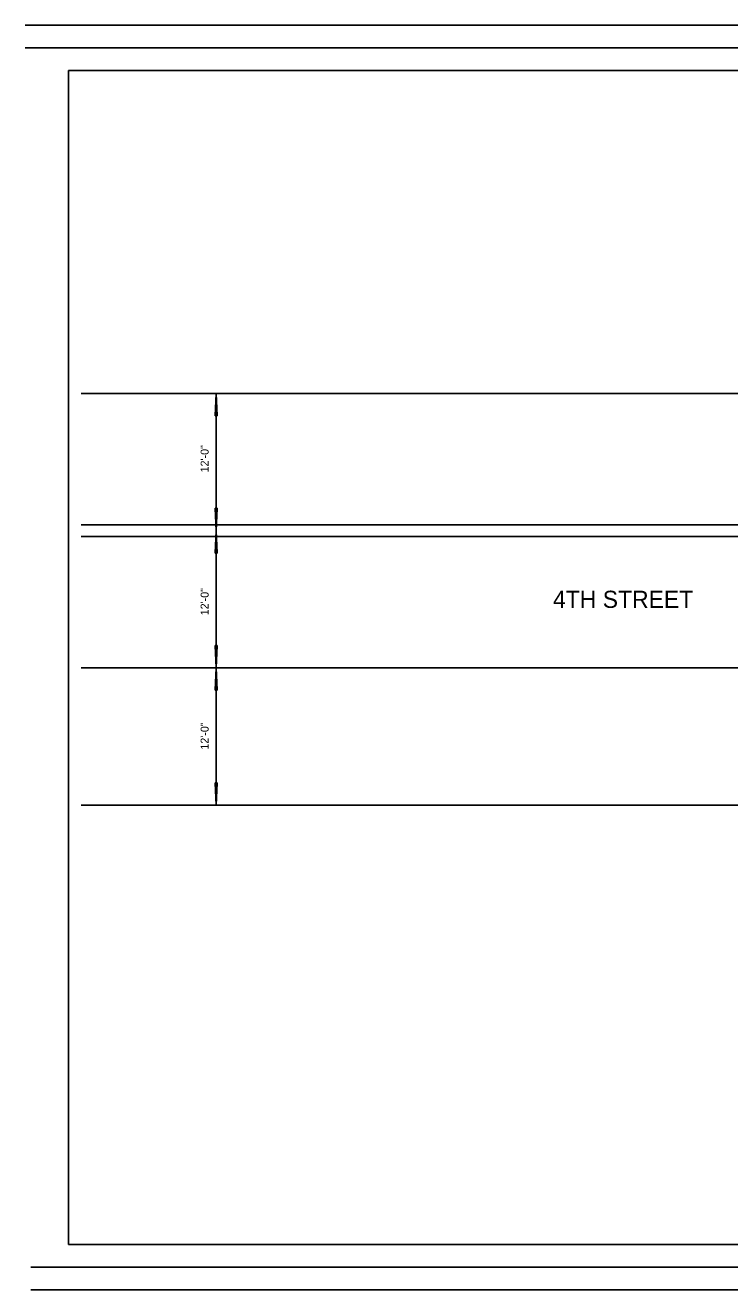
# Model space of a CAD drawing. Extents: x 1944905 to 1956777, y 763871 to 764977.
# Drawn here: x 1948322 to 1948938, y 763871 to 764977 of the extents above; entities that cross this region are included whole.
import ezdxf

# ---------------------------------------------------------------- set-up
doc = ezdxf.new("R2010")
doc.units = 0
doc.layers.add('Default', color=7, linetype='Continuous')
doc.layers.add('R_Horz Alg', color=7, linetype='Continuous')

msp = doc.modelspace()

# ---------------------------------------------------------------- linework, layer by layer
at = {"layer": 'Default'}
for p, q in [((1949941, 764976.7), (1948322.3, 764976.7)), ((1949941, 764957), (1948322.3, 764957)), ((1948360.1, 764937.3), (1949941, 764937.3)), ((1948360.1, 763910.1), (1948360.1, 764937.3)), ((1948488.2, 764635.1), (1948489.2, 764654.6)), ((1948489.2, 764654.6), (1948490.1, 764635.1)), ((1948489.2, 764534.6), (1948489.2, 764654.6)), ((1948490.1, 764635.1), (1948488.2, 764635.1)), ((1948488.2, 764635), (1948488.2, 764635.1)), ((1948489.2, 764534.6), (1948488.2, 764554.2)), ((1948488.2, 764554.2), (1948490.1, 764554.2)), ((1948490.1, 764554.2), (1948489.2, 764534.6)), ((1948490.1, 764554.2), (1948490.1, 764554.2)), ((1948488.2, 764515.1), (1948489.2, 764534.6)), ((1948489.2, 764534.6), (1948490.1, 764515.1)), ((1948489.2, 764414.6), (1948489.2, 764534.6)), ((1948490.1, 764515.1), (1948488.2, 764515.1)), ((1948488.2, 764515), (1948488.2, 764515.1)), ((1948489.2, 764414.6), (1948488.2, 764434.2)), ((1948488.2, 764434.2), (1948490.1, 764434.2)), ((1948490.1, 764434.2), (1948489.2, 764414.6)), ((1948490.1, 764434.2), (1948490.1, 764434.2)), ((1948488.2, 764395.1), (1948489.2, 764414.6)), ((1948489.2, 764414.6), (1948490.1, 764395.1)), ((1948489.2, 764294.6), (1948489.2, 764414.6)), ((1948490.1, 764395.1), (1948488.2, 764395.1)), ((1948488.2, 764395), (1948488.2, 764395.1)), ((1948489.2, 764294.6), (1948488.2, 764314.2)), ((1948488.2, 764314.2), (1948490.1, 764314.2)), ((1948490.1, 764314.2), (1948489.2, 764294.6)), ((1948490.1, 764314.2), (1948490.1, 764314.2)), ((1949941, 763910.1), (1948360.1, 763910.1)), ((1948327.3, 763890.4), (1949941, 763890.4)), ((1948327.3, 763870.7), (1949941, 763870.7))]:
    msp.add_line(p, q, dxfattribs=at)
at = {"layer": 'R_Horz Alg'}
for p, q in [((1948371.2, 764654.6), (1949337, 764654.6)), ((1948371.2, 764539.6), (1949371.2, 764539.6)), ((1948371.2, 764529.6), (1949371.2, 764529.6)), ((1948371.2, 764414.6), (1949371.2, 764414.6)), ((1948371.2, 764294.6), (1949342.8, 764294.6))]:
    msp.add_line(p, q, dxfattribs=at)

# ---------------------------------------------------------------- texts
at = {"layer": 'Default'}
for p in [(1948482.6, 764585.6), (1948482.6, 764460.6), (1948482.6, 764343.1)]:
    msp.add_text('12\'-0"', height=7, rotation=90, dxfattribs=at).set_placement(p)
msp.add_text('4TH STREET', height=15, dxfattribs=at).set_placement((1948783.6, 764467.1))

doc.saveas('drawing.dxf')
